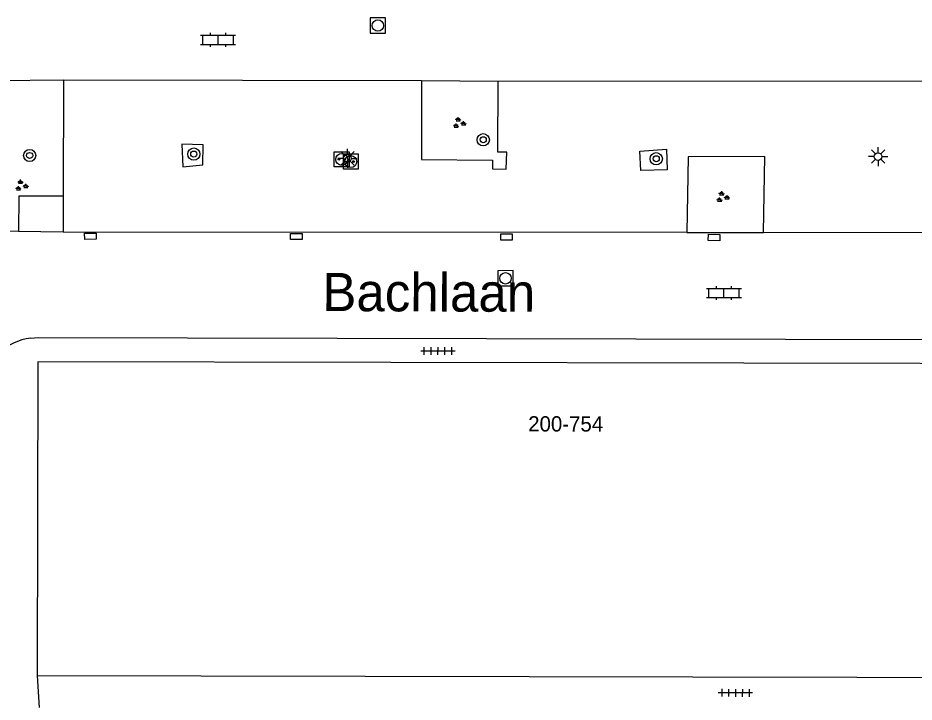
# Model space of a CAD drawing. Extents: x 132999 to 136000, y 398499 to 400501.
# Drawn here: x 134386.1 to 134444.8, y 399105.3 to 399150.1 of the extents above; entities that cross this region are included whole.
import ezdxf

# ---------------------------------------------------------------- set-up
doc = ezdxf.new("R2010")
doc.units = 0
for name, color, linetype in [('gg-anno-huisnummerreeks BGT', 7, 'Continuous'), ('gg-anno-openbare ruimte label', 7, 'Continuous'), ('gg-bbg-hoofdgebouw', 7, 'Continuous'), ('gg-knt-verharding', 7, 'Continuous'), ('gg-knt-verharding nz', 7, 'Continuous'), ('gt-grn-weggrens', 7, 'Continuous'), ('gt-symb-boom', 7, 'Continuous'), ('gt-symb-groenvak', 7, 'Continuous'), ('gt-symb-klinker verharding', 7, 'Continuous'), ('gt-symb-kolk center center', 7, 'Continuous'), ('gt-symb-laadpunt elektrisch vervoer', 7, 'Continuous'), ('gt-symb-lichtmast', 7, 'Continuous'), ('gt-symb-rioolschacht', 7, 'Continuous'), ('gt-symb-tegel verharding', 7, 'Continuous')]:
    doc.layers.add(name, color=color, linetype=linetype)

# ---------------------------------------------------------------- blocks, each defined once
blk = doc.blocks.new('gt0-BOOM')
at = {"layer": 'gt-symb-boom'}
for radius in [0.4, 0.2]:
    blk.add_circle((0, 0), radius, dxfattribs=at)
blk = doc.blocks.new('gt0-GRVAK')
at = {"layer": 'gt-symb-groenvak'}
for p, q in [((-0.11, 0.189), (-0.228, 0.24)), ((-0.182, 0.153), (0.088, 0.153)), ((-0.091, 0.211), (-0.156, 0.322)), ((-0.047, 0.214), (-0.047, 0.393)), ((-0.004, 0.211), (0.061, 0.322)), ((0.015, 0.189), (0.133, 0.24)), ((0.262, -0.052), (0.197, 0.059)), ((0.305, -0.049), (0.305, 0.13)), ((0.349, -0.052), (0.414, 0.059)), ((-0.245, -0.228), (-0.363, -0.177)), ((-0.318, -0.264), (-0.047, -0.264)), ((-0.226, -0.206), (-0.291, -0.095)), ((-0.183, -0.203), (-0.183, -0.024)), ((-0.139, -0.206), (-0.074, -0.095)), ((-0.12, -0.228), (-0.002, -0.177)), ((0.243, -0.074), (0.125, -0.023)), ((0.17, -0.11), (0.441, -0.11)), ((0.368, -0.074), (0.486, -0.023))]:
    blk.add_line(p, q, dxfattribs=at)
blk = doc.blocks.new('gt0-LMAST')
at = {"layer": 'gt-symb-lichtmast'}
for p, q in [((-0.005, 0.246), (-0.005, 0.621)), ((-0.182, 0.173), (-0.447, 0.438)), ((0.172, 0.173), (0.437, 0.438)), ((-0.255, -0.004), (-0.63, -0.004)), ((-0.182, -0.181), (-0.447, -0.446)), ((-0.005, -0.254), (-0.005, -0.629)), ((0.437, -0.446), (0.172, -0.181)), ((0.245, -0.004), (0.62, -0.004))]:
    blk.add_line(p, q, dxfattribs=at)
blk.add_circle((-0.005, -0.004), 0.25, dxfattribs=at)
blk = doc.blocks.new('gt0-KOLKCC')
at = {"layer": 'gt-symb-kolk center center'}
blk.add_lwpolyline([(-0.375, 0.2), (0.375, 0.2), (0.375, -0.2), (-0.375, -0.2)], close=True, dxfattribs=at)
blk = doc.blocks.new('gt0-KL1')
at = {"layer": 'gt-symb-klinker verharding'}
for p, q in [((-1.15, 0.3), (1.15, 0.3)), ((-1, -0.3), (-1, 0.3)), ((-0.5, 0.3), (-0.5, 0.45)), ((0, -0.3), (0, 0.3)), ((0.5, 0.3), (0.5, 0.45)), ((1, -0.3), (1, 0.3)), ((-1.15, -0.3), (1.15, -0.3)), ((-0.5, -0.45), (-0.5, -0.3)), ((0.5, -0.45), (0.5, -0.3))]:
    blk.add_line(p, q, dxfattribs=at)
blk = doc.blocks.new('gt0-LEV')
at = {"layer": 'gt-symb-laadpunt elektrisch vervoer'}
blk.add_lwpolyline([(-0.486, 0.501), (0.486, 0.501), (0.486, -0.499), (-0.486, -0.499)], close=True, dxfattribs=at)
for centre, radius in [((0, 0), 0.393), ((-0.186, 0), 0.0566), ((0.186, 0), 0.0566)]:
    blk.add_circle(centre, radius, dxfattribs=at)
blk = doc.blocks.new('gt0-RS')
at = {"layer": 'gt-symb-rioolschacht'}
blk.add_lwpolyline([(-0.5, -0.5), (0.5, -0.5), (0.5, 0.5), (-0.5, 0.5)], close=True, dxfattribs=at)
blk.add_circle((0, 0), 0.375, dxfattribs=at)
blk = doc.blocks.new('gt0-TEG1')
at = {"layer": 'gt-symb-tegel verharding'}
for p, q in [((-1.125, 0), (1.125, 0)), ((-0.9, -0.25), (-0.9, 0.25)), ((-0.45, -0.25), (-0.45, 0.25)), ((0, -0.25), (0, 0.25)), ((0.45, -0.25), (0.45, 0.25)), ((0.9, -0.25), (0.9, 0.25))]:
    blk.add_line(p, q, dxfattribs=at)

msp = doc.modelspace()

# ---------------------------------------------------------------- linework, layer by layer
at = {"layer": 'gg-bbg-hoofdgebouw'}
for points in [[(134456.803, 399127.433), (134387.45, 399127.558), (134387.411, 399107)], [(134465.289, 399107.439), (134464.49, 399107.54), (134464.57, 399108.28), (134462.58, 399108.55), (134462.58, 399106.85), (134387.411, 399107)]]:
    msp.add_lwpolyline(points, dxfattribs=at)
at = {"layer": 'gg-knt-verharding'}
for p, q in [((134389.121, 399146.02), (134389.113, 399138.4)), ((134412.581, 399145.99), (134417.591, 399145.94)), ((134417.573, 399141.301), (134417.591, 399145.94)), ((134389.113, 399138.4), (134389.111, 399136.05)), ((134389.111, 399136.05), (134386.182, 399136.089)), ((134429.96, 399136.03), (134434.981, 399136.04)), ((134386.987, 399129.105), (134387.468, 399129.145)), ((134387.468, 399129.145), (134456.788, 399128.991))]:
    msp.add_line(p, q, dxfattribs=at)
for points in [[(134386.182, 399136.089), (134384.651, 399136.11), (134384.731, 399145.98), (134389.121, 399146.02)], [(134412.581, 399145.99), (134412.571, 399140.8), (134417.22, 399140.763)], [(134396.881, 399141.809), (134396.944, 399140.329), (134398.246, 399140.459), (134398.28, 399141.772), (134396.881, 399141.809)], [(134417.22, 399140.763), (134417.216, 399140.208), (134418.117, 399140.169), (134418.166, 399141.299), (134417.573, 399141.301)], [(134426.936, 399140.085), (134426.88, 399141.349), (134428.612, 399141.482), (134428.657, 399140.141), (134426.936, 399140.085)], [(134434.981, 399136.04), (134435.071, 399141), (134430.051, 399140.99), (134429.96, 399136.03)], [(134389.113, 399138.4), (134386.213, 399138.403), (134386.182, 399136.089)]]:
    msp.add_lwpolyline(points, dxfattribs=at)
msp.add_arc((134387.344, 399125.701), 3.423, 95.99363, 173.93108, dxfattribs=at)
at = {"layer": 'gg-knt-verharding nz'}
for p, q in [((134389.121, 399146.02), (134412.581, 399145.99)), ((134417.591, 399145.94), (134454.991, 399145.98)), ((134429.96, 399136.03), (134389.111, 399136.05)), ((134454.811, 399135.98), (134434.981, 399136.04))]:
    msp.add_line(p, q, dxfattribs=at)
at = {"layer": 'gt-grn-weggrens'}
msp.add_line((134387.411, 399107), (134387.543, 399104.92), dxfattribs=at)

# ---------------------------------------------------------------- block references
at = {"layer": 'gt-symb-boom'}
for p in [(134416.622, 399142.103), (134397.665, 399141.165), (134386.914, 399141.073), (134427.952, 399140.86)]:
    msp.add_blockref('gt0-BOOM', p, dxfattribs=at)
at = {"layer": 'gt-symb-groenvak'}
for p in [(134415.032, 399143.194), (134386.364, 399139.097), (134432.283, 399138.352)]:
    msp.add_blockref('gt0-GRVAK', p, dxfattribs=at)
at = {"layer": 'gt-symb-klinker verharding'}
for p in [(134399.255, 399148.646), (134432.387, 399132.07)]:
    msp.add_blockref('gt0-KL1', p, dxfattribs=at)
at = {"layer": 'gt-symb-kolk center center'}
for p, rotation in [((134390.89, 399135.786), 0.9166542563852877), ((134404.376, 399135.765), 179.88540859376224), ((134418.147, 399135.736), 0.22918189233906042), ((134431.742, 399135.701), -1.5466102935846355)]:
    msp.add_blockref('gt0-KOLKCC', p, dxfattribs=dict(at, rotation=rotation))
at = {"layer": 'gt-symb-laadpunt elektrisch vervoer'}
for p in [(134407.354, 399140.818), (134407.944, 399140.672)]:
    msp.add_blockref('gt0-LEV', p, dxfattribs=at)
at = {"layer": 'gt-symb-lichtmast'}
for p in [(134442.488, 399141.006), (134407.733, 399140.887)]:
    msp.add_blockref('gt0-LMAST', p, dxfattribs=at)
at = {"layer": 'gt-symb-rioolschacht'}
for p, rotation in [((134409.722, 399149.581), -0.057295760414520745), ((134418.078, 399133.03), 0.05729576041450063)]:
    msp.add_blockref('gt0-RS', p, dxfattribs=dict(at, rotation=rotation))
at = {"layer": 'gt-symb-tegel verharding'}
for p, rotation in [((134413.657, 399128.276), -0.11459140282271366), ((134433.139, 399105.88), 179.7708181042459)]:
    msp.add_blockref('gt0-TEG1', p, dxfattribs=dict(at, rotation=rotation))

# ---------------------------------------------------------------- texts
at = {"layer": 'gg-anno-huisnummerreeks BGT'}
msp.add_text('200-754', height=1, rotation=359.9, dxfattribs=at).set_placement((134419.564, 399122.999))
at = {"layer": 'gg-anno-openbare ruimte label'}
msp.add_text('Bachlaan', height=2.5, rotation=359.8, dxfattribs=at).set_placement((134406.079, 399130.883))

doc.saveas('drawing.dxf')
